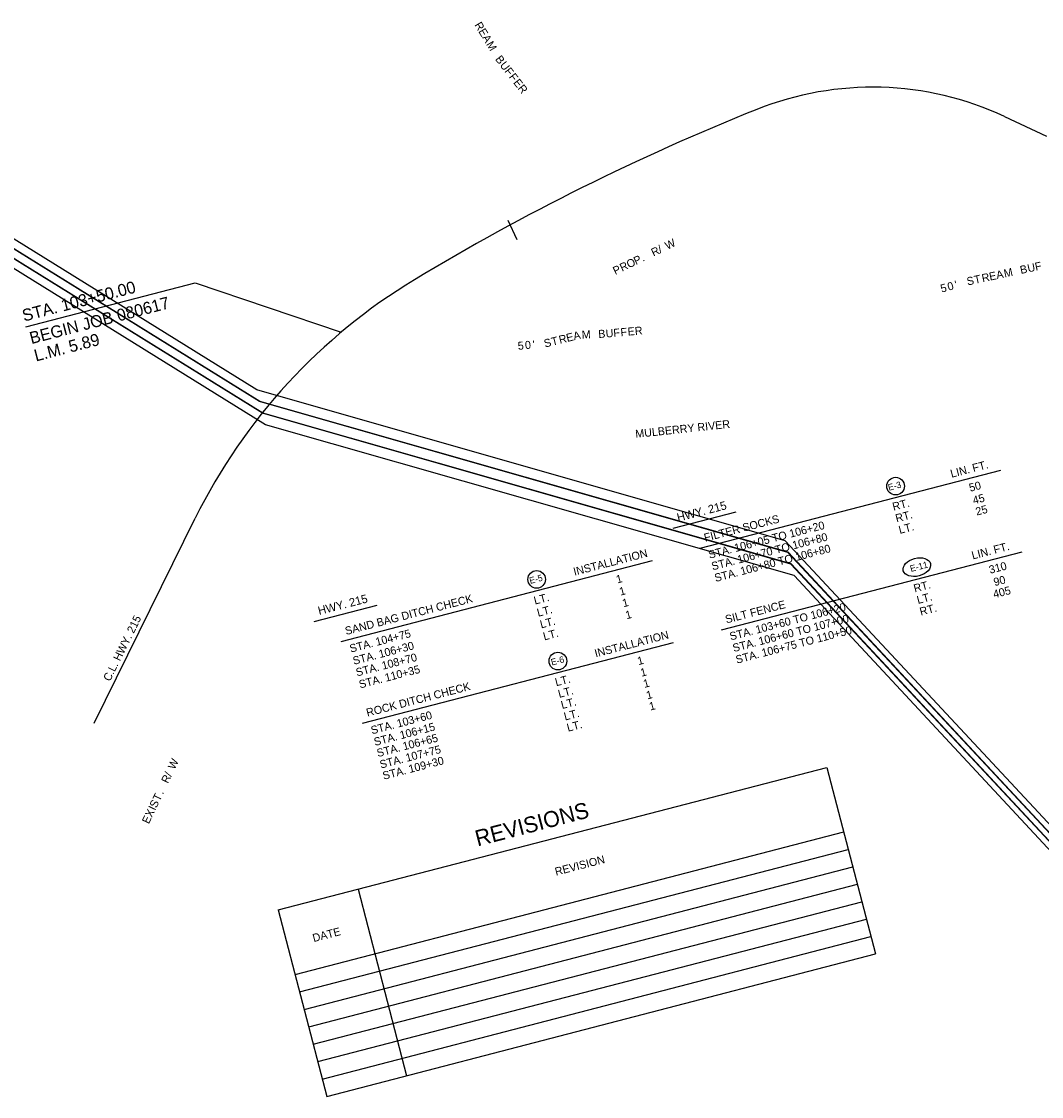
# Model space of a CAD drawing. Extents: x 833706 to 836451, y 495860 to 497794.
# Drawn here: x 834921 to 835686, y 496180 to 496986 of the extents above; entities that cross this region are included whole.
import ezdxf

# ---------------------------------------------------------------- set-up
doc = ezdxf.new("R2010")
doc.units = 0
for name, color, linetype in [('1', 7, 'Continuous'), ('44', 7, 'Continuous'), ('8', 7, 'Continuous'), ('Default', 7, 'Continuous'), ('R_Draft', 7, 'Continuous'), ('R_Horz Alg', 7, 'Continuous'), ('R_Horz Alg Stationing', 7, 'Continuous')]:
    doc.layers.add(name, color=color, linetype=linetype)

msp = doc.modelspace()

# ---------------------------------------------------------------- linework, layer by layer
at = {"layer": '1'}
for centre in [(835576.16, 496637.79), (835307.06, 496567.87), (835322.97, 496506.62)]:
    msp.add_circle(centre, 6.61, dxfattribs=at)
msp.add_ellipse((835592.08, 496577.04), major_axis=(10.18, 2.65), ratio=0.638788, dxfattribs=at)
at = {"layer": '44'}
for p, q in [((835429.66, 496591.23), (835654.98, 496649.77)), ((835409.37, 496606.2), (835456.64, 496618.48)), ((835160.56, 496521.31), (835393.82, 496581.92)), ((835445.58, 496529.98), (835670.9, 496588.52)), ((835140.27, 496536.28), (835187.54, 496548.56)), ((835176.47, 496460.06), (835409.74, 496520.66))]:
    msp.add_line(p, q, dxfattribs=at)
at = {"layer": '8'}
msp.add_line((835051.15, 496790.13), (835160.53, 496753.26), dxfattribs=at)
msp.add_lwpolyline([(834924.08, 496757.12), (835051.15, 496790.13)], dxfattribs=at)
at = {"layer": 'Default'}
for p, q in [((835113.37, 496320), (835524.71, 496426.87)), ((835524.71, 496426.87), (835561.05, 496287.02)), ((835125.94, 496271.61), (835537.28, 496378.48)), ((835129.34, 496258.54), (835540.68, 496365.42)), ((835132.73, 496245.48), (835544.08, 496352.35)), ((835136.13, 496232.41), (835547.47, 496339.28)), ((835136.13, 496232.41), (835547.47, 496339.28)), ((835173.19, 496335.54), (835209.53, 496195.69)), ((835139.52, 496219.34), (835550.86, 496326.22)), ((835113.37, 496320), (835149.71, 496180.14)), ((835142.92, 496206.28), (835554.26, 496313.15)), ((835146.31, 496193.21), (835557.65, 496300.09)), ((835149.71, 496180.14), (835561.05, 496287.02))]:
    msp.add_line(p, q, dxfattribs=at)
at = {"layer": 'R_Draft'}
for points in [[(835097.15, 496709.88), (834733.11, 496935.95), (833783.44, 497794.34)], [(835099.26, 496701.13), (834735.21, 496927.2), (833785.55, 497785.59)], [(835099.42, 496701.17), (834735.37, 496927.24), (833785.71, 497785.63)], [(835099.44, 496701.18), (834735.39, 496927.25), (833785.73, 497785.63)], [(835101.52, 496692.42), (834737.47, 496918.49), (833787.81, 497776.87)], [(835101.54, 496692.42), (834737.5, 496918.5), (833787.83, 497776.88)], [(835101.7, 496692.47), (834737.66, 496918.54), (833787.99, 497776.92)], [(835103.81, 496683.71), (834739.76, 496909.79), (833790.1, 497768.17)], [(835693.41, 496382.1), (835493.34, 496596.87), (835097.15, 496709.88)], [(835695.52, 496373.35), (835495.44, 496588.12), (835099.26, 496701.13)], [(835695.68, 496373.39), (835495.6, 496588.16), (835099.42, 496701.17)], [(835695.7, 496373.4), (835495.62, 496588.17), (835099.44, 496701.18)], [(835697.78, 496364.64), (835497.7, 496579.41), (835101.52, 496692.42)], [(835697.8, 496364.64), (835497.73, 496579.41), (835101.54, 496692.42)], [(835697.96, 496364.69), (835497.89, 496579.45), (835101.7, 496692.47)], [(835700.07, 496355.93), (835499.99, 496570.7), (835103.81, 496683.71)]]:
    msp.add_lwpolyline(points, dxfattribs=at)
at = {"layer": 'R_Horz Alg'}
for p, q in [((835657.74, 496914.96), (835689.37, 496900.19)), ((834975.23, 496460.02), (835051.15, 496613.79))]:
    msp.add_line(p, q, dxfattribs=at)
for centre, radius, start, end in [((835558.82, 496703.05), 233.86, 64.975, 111.7875), ((836126.36, 495283.19), 1762.95, 111.7875, 121.11111), ((835438.88, 496422.34), 432.42, 121.11111, 153.72222)]:
    msp.add_arc(centre, radius, start, end, dxfattribs=at)
at = {"layer": 'R_Horz Alg Stationing'}
msp.add_lwpolyline([(835285.33, 496837.22), (835292.27, 496822.8)], dxfattribs=at)

# ---------------------------------------------------------------- texts
at = {"layer": '1'}
for s, rotation, p in [('E-3 ', 14.56436, (835571.14, 496634.33)), ('E-11', 14.56434, (835587.64, 496573.45)), ('E-5 ', 14.56436, (835302.26, 496564.47)), ('E-6 ', 14.56436, (835318.47, 496503.3))]:
    msp.add_text(s, height=4.8, rotation=rotation, dxfattribs=at).set_placement(p)
at = {"layer": '44'}
for s, height, rotation, p in [('LIN. FT.', 6, 14.56434, (835618.09, 496644.06)), ('50', 6, 14.56436, (835632.07, 496633.55)), ('45', 6, 14.56436, (835634.79, 496624.1)), ('HWY. 215', 6.25, 14.56436, (835413.11, 496611.08)), ('RT.', 6, 14.56434, (835574.62, 496619.32)), ('25', 6, 14.56436, (835636.98, 496615.69)), ('FILTER SOCKS', 6, 14.56434, (835433.36, 496596.07)), ('RT.', 6, 14.56434, (835576.88, 496610.61)), ('STA. 106+05 TO 106+20', 6, 14.56434, (835436.67, 496583.33)), ('LT.', 6, 14.56434, (835579.28, 496601.94)), ('STA. 106+70 TO 106+80', 6, 14.56434, (835438.93, 496574.62)), ('INSTALLATION', 6, 14.56436, (835335.43, 496570.62)), ('STA. 106+80 TO 106+80', 6, 14.56434, (835441.19, 496565.91)), ('LIN. FT.', 6, 14.56434, (835634, 496582.81)), ('310', 6, 14.56436, (835647.02, 496572.05)), ('1', 6, 14.56436, (835367.47, 496564.8)), ('RT.', 6, 14.56434, (835590.53, 496558.07)), ('90', 6, 14.56436, (835650.46, 496562.79)), ('HWY. 215', 6.25, 14.56436, (835144.01, 496541.16)), ('SAND BAG DITCH CHECK', 6, 14.56436, (835164.25, 496526.15)), ('LT.', 6, 14.56436, (835305.78, 496548.95)), ('1', 6, 14.56436, (835369.85, 496555.66)), ('LT.', 6, 14.56434, (835592.93, 496549.4)), ('405', 6, 14.56436, (835650.06, 496553.7)), ('1', 6, 14.56436, (835372.11, 496546.95)), ('SILT FENCE      ', 6, 14.56434, (835449.27, 496534.82)), ('STA. 103+60 TO 106+20', 6, 14.56434, (835452.58, 496522.08)), ('RT.', 6, 14.56434, (835595.06, 496540.65)), ('LT.', 6, 14.56436, (835308.16, 496539.8)), ('1', 6, 14.56436, (835374.45, 496537.95)), ('STA. 106+60 TO 107+00', 6, 14.56434, (835454.84, 496513.37)), ('LT.', 6, 14.56436, (835310.42, 496531.09)), ('STA. 106+75 TO 110+50', 6, 14.56434, (835457.11, 496504.66)), ('STA. 104+75', 6, 14.56436, (835167.69, 496512.92)), ('LT.', 6, 14.56436, (835312.76, 496522.1)), ('INSTALLATION', 6, 14.56436, (835351.34, 496509.37)), ('STA. 106+30', 6, 14.56436, (835170.07, 496503.77)), ('STA. 108+70', 6, 14.56436, (835172.33, 496495.06)), ('1', 6, 14.56436, (835383.38, 496503.55)), ('STA. 110+35', 6, 14.56436, (835174.67, 496486.07)), ('1', 6, 14.56436, (835385.65, 496494.84)), ('LT.', 6, 14.56436, (835321.7, 496487.7)), ('1', 6, 14.56436, (835387.82, 496486.48)), ('ROCK DITCH CHECK', 6, 14.56436, (835180.17, 496464.9)), ('LT.', 6, 14.56436, (835323.96, 496478.99)), ('1', 6, 14.56436, (835390.05, 496477.89)), ('LT.', 6, 14.56436, (835326.13, 496470.63)), ('STA. 103+60', 6, 14.56436, (835183.61, 496451.67)), ('LT.', 6, 14.56436, (835328.36, 496462.03)), ('1', 6, 14.56436, (835392.24, 496469.48)), ('STA. 106+15', 6, 14.56436, (835185.87, 496442.96)), ('LT.', 6, 14.56436, (835330.55, 496453.63)), ('STA. 106+65', 6, 14.56436, (835188.04, 496434.6)), ('STA. 107+75', 6, 14.56436, (835190.27, 496426)), ('STA. 109+30', 6, 14.56436, (835192.46, 496417.6))]:
    msp.add_text(s, height=height, rotation=rotation, dxfattribs=at).set_placement(p)
at = {"layer": '8'}
for s, height, rotation, p in [('R', 6, 301.06588, (835260.22, 496983.61)), ('E', 6, 301.06588, (835263.15, 496978.75)), ('A', 6, 301.06588, (835265.93, 496974.14)), ('M', 6, 301.06588, (835268.95, 496969.12)), ('B', 6, 307.74933, (835275.63, 496957.82)), ('U', 6, 307.74933, (835279.1, 496953.34)), ('F', 6, 307.74933, (835282.63, 496948.78)), ('F', 6, 307.74933, (835285.93, 496944.52)), ('E', 6, 307.74933, (835289.23, 496940.26)), ('R', 6, 307.74933, (835292.52, 496936)), ('W', 6, 25.6769, (835405.02, 496814.89)), ('R', 6, 25.6769, (835394.63, 496809.89)), ('/', 6, 25.6769, (835399.74, 496812.35)), ('O', 6, 25.6769, (835376.2, 496801.03)), ('P', 6, 25.6769, (835381.48, 496803.57)), ('.', 6, 25.6769, (835386.59, 496806.02)), ('P', 6, 25.6769, (835365.98, 496796.12)), ('R', 6, 25.6769, (835371.09, 496798.57)), ('E', 6, 12.15375, (835646.95, 496791.85)), ('A', 6, 12.15375, (835652.21, 496792.99)), ('M', 6, 12.15375, (835657.94, 496794.22)), ('B', 6, 12.19776, (835670.09, 496796.84)), ('U', 6, 12.19776, (835675.63, 496798.04)), ('F', 6, 12.19776, (835681.26, 496799.26)), ('STA. 103+50.00', 9, 14.55565, (834922.71, 496761.13)), ('0', 6, 15.25756, (835615.89, 496784.25)), ("'", 6, 15.25756, (835621.55, 496785.79)), ('S', 6, 12.15375, (835630.14, 496788.23)), ('T', 6, 12.15375, (835635.68, 496789.43)), ('R', 6, 12.15375, (835641.41, 496790.66)), ('5', 6, 15.25756, (835610.7, 496782.83)), ('BEGIN JOB 080617', 9, 14.55565, (834928.25, 496744.25)), ('L.M. 5.89', 9, 14.55565, (834931.64, 496731.19)), ('R', 6, 14.04888, (835324.52, 496744.48)), ('E', 6, 14.04888, (835330.02, 496745.86)), ('A', 6, 14.04888, (835335.24, 496747.17)), ('M', 6, 2.56072, (835340.96, 496748.36)), ('B', 6, 2.56072, (835353.37, 496748.91)), ('U', 6, 5.08824, (835359.04, 496749.15)), ('F', 6, 5.08824, (835364.78, 496749.66)), ('F', 6, 5.08824, (835370.14, 496750.14)), ('E', 6, 5.08824, (835375.51, 496750.62)), ('R', 6, 5.08824, (835380.87, 496751.09)), ('5', 6, 5.90345, (835293.22, 496739.91)), ('0', 6, 5.90345, (835298.58, 496740.47)), ("'", 6, 5.90345, (835304.4, 496741.07)), ('S', 6, 14.04888, (835313.34, 496741.68)), ('T', 6, 14.04888, (835318.84, 496743.06)), ('MULBERRY RIVER', 6, 6.1285, (835381.34, 496673.92)), ('C.L. HWY. 215', 6, 63.72222, (834987.16, 496490.97)), ('W', 6, 64.53099, (835035.66, 496424.82)), ('R', 6, 64.53099, (835030.71, 496414.42)), ('/', 6, 64.53099, (835033.14, 496419.53)), ('T', 6, 64.53099, (835024.35, 496401.06)), ('.', 6, 64.53099, (835026.87, 496406.35)), ('X', 6, 64.53099, (835018.58, 496388.95)), ('I', 6, 64.53099, (835021.06, 496394.16)), ('S', 6, 64.53099, (835021.91, 496395.95)), ('E', 6, 64.53099, (835016.26, 496384.09))]:
    msp.add_text(s, height=height, rotation=rotation, dxfattribs=at).set_placement(p)
at = {"layer": 'Default'}
for s, height, p in [('REVISIONS', 12, (835262.7, 496367.58)), ('REVISION', 6, (835321.59, 496345.69)), ('DATE', 6, (835139.92, 496295.9))]:
    msp.add_text(s, height=height, rotation=14.56436, dxfattribs=at).set_placement(p)

doc.saveas('drawing.dxf')
